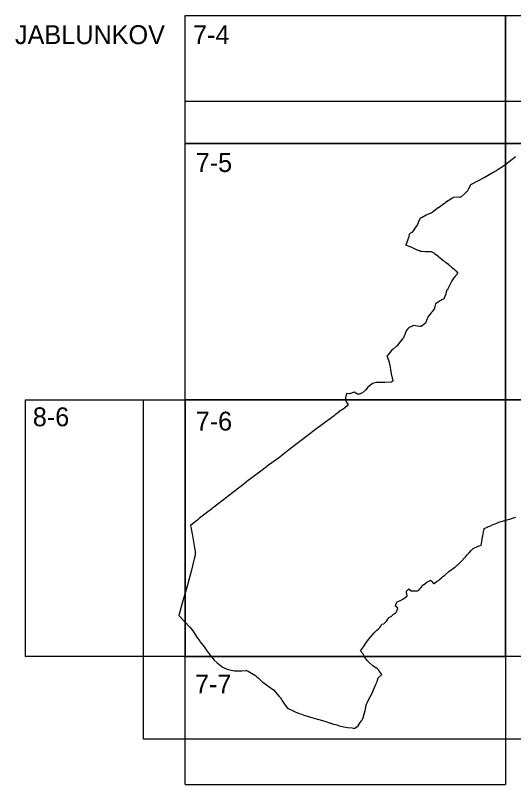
# Model space of a CAD drawing. Extents: x -447352 to -425530, y -1135906 to -1121091.
# Drawn here: x -443419.6 to -443176.6, y -1126653.4 to -1126278.4 of the extents above; entities that cross this region are included whole.
import ezdxf

# ---------------------------------------------------------------- set-up
doc = ezdxf.new("R2010")
doc.units = 0
for name, color, linetype in [('Vrstva 1', 7, 'Continuous'), ('Vrstva 10', 7, 'Continuous'), ('Vrstva 4', 7, 'Continuous')]:
    doc.layers.add(name, color=color, linetype=linetype)

msp = doc.modelspace()

# ---------------------------------------------------------------- linework, layer by layer
at = {"layer": 'Vrstva 1'}
for points in [[(-443175.66, -1126347.4), (-443176.81, -1126348.27), (-443177.38, -1126348.7), (-443177.96, -1126349.14), (-443178.12, -1126349.26), (-443180.25, -1126350.9), (-443181.32, -1126351.72), (-443181.79, -1126352.06), (-443182.55, -1126352.57), (-443182.8, -1126352.73), (-443183.39, -1126353.12), (-443183.43, -1126353.15), (-443183.64, -1126353.29), (-443184.55, -1126353.89), (-443184.56, -1126353.89), (-443185.03, -1126354.15), (-443185.18, -1126354.23), (-443185.36, -1126354.33), (-443185.82, -1126354.58), (-443186, -1126354.69), (-443186.16, -1126354.78), (-443186.26, -1126354.84), (-443186.5, -1126354.98), (-443188.16, -1126355.92), (-443188.33, -1126356.01), (-443188.56, -1126356.14), (-443191.03, -1126357.54), (-443191.15, -1126357.61), (-443193.26, -1126358.74), (-443194.28, -1126359.29), (-443197.62, -1126361.1), (-443197.79, -1126361.4), (-443197.85, -1126361.51), (-443198.63, -1126362.97), (-443199.31, -1126364.29), (-443199.45, -1126364.42), (-443199.54, -1126364.5), (-443200.68, -1126365.54), (-443202.19, -1126366.92), (-443202.36, -1126367.07), (-443202.36, -1126367.08), (-443202.83, -1126367.09), (-443206.02, -1126367.18), (-443206.03, -1126367.18), (-443206.46, -1126367.47), (-443207.29, -1126368.04), (-443209.76, -1126369.7), (-443209.8, -1126369.72), (-443210.04, -1126369.9), (-443210.31, -1126370.1), (-443213.29, -1126372.23), (-443213.36, -1126372.28), (-443216.36, -1126374.46), (-443216.83, -1126374.8), (-443216.99, -1126374.86), (-443218.93, -1126375.58), (-443218.94, -1126375.58), (-443219.33, -1126375.82), (-443221.21, -1126376.98), (-443222.13, -1126377.19), (-443222.38, -1126377.7), (-443223.14, -1126379.21), (-443223.15, -1126379.22), (-443223.22, -1126379.48), (-443223.42, -1126380.32), (-443224.25, -1126381.43), (-443225.62, -1126383.38), (-443226.18, -1126384.19), (-443226.21, -1126384.21), (-443227.37, -1126384.85), (-443227.47, -1126384.91), (-443227.54, -1126385.3), (-443227.69, -1126386.11), (-443227.74, -1126386.3), (-443229.03, -1126389.88), (-443229.2, -1126390.36), (-443229.17, -1126390.35), (-443229.15, -1126390.34), (-443228.47, -1126390.6), (-443226.66, -1126391.26), (-443226.04, -1126391.55), (-443223.75, -1126392.63), (-443223.73, -1126392.63), (-443222.57, -1126393.1), (-443222.1, -1126393.28), (-443222.07, -1126393.29), (-443221.64, -1126393.32), (-443221.5, -1126393.33), (-443221.28, -1126393.35), (-443219.68, -1126393.45), (-443218.64, -1126393.52), (-443217.59, -1126393.49), (-443216.75, -1126393.46), (-443216.74, -1126393.46), (-443216.46, -1126393.61), (-443216.09, -1126393.87), (-443215.54, -1126394.25), (-443215.15, -1126394.53), (-443213.59, -1126395.67), (-443213.42, -1126395.79), (-443212.31, -1126396.71), (-443211.92, -1126397.03), (-443211.74, -1126397.18), (-443210.99, -1126397.79), (-443210.72, -1126398.02), (-443210.12, -1126398.51), (-443209.9, -1126398.69), (-443209.26, -1126399.11), (-443208.51, -1126399.61), (-443208.48, -1126399.63), (-443207.72, -1126400.31), (-443206.84, -1126401.09), (-443206.4, -1126401.47), (-443205.39, -1126402.36), (-443205.13, -1126402.59), (-443205.08, -1126402.64), (-443204.98, -1126402.74), (-443204.97, -1126402.75), (-443204.88, -1126402.85), (-443204.85, -1126402.88), (-443203.8, -1126404.11), (-443203.81, -1126404.12), (-443204.25, -1126404.61), (-443204.31, -1126404.68), (-443204.88, -1126405.31), (-443205.7, -1126406.37), (-443205.87, -1126406.58), (-443206.43, -1126407.3), (-443206.73, -1126407.83), (-443206.75, -1126407.87), (-443206.76, -1126407.89), (-443206.89, -1126408.17), (-443207.69, -1126409.84), (-443208, -1126410.48), (-443208.62, -1126411.77), (-443208.73, -1126412.01), (-443208.74, -1126412.01), (-443208.78, -1126412.04), (-443209.07, -1126412.24), (-443209.15, -1126412.28), (-443209.2, -1126412.38), (-443209.29, -1126412.58), (-443209.38, -1126412.86), (-443209.55, -1126413.42), (-443209.56, -1126413.44), (-443209.68, -1126413.94), (-443209.7, -1126414.01), (-443209.69, -1126414.07), (-443209.68, -1126414.15), (-443209.68, -1126414.22), (-443209.69, -1126414.27), (-443210.57, -1126416.6), (-443210.59, -1126416.65), (-443210.61, -1126416.69), (-443210.62, -1126416.7), (-443211.32, -1126417), (-443211.57, -1126417.11), (-443212.04, -1126417.35), (-443214.65, -1126419.04), (-443214.65, -1126419.04), (-443215.02, -1126420.35), (-443215.1, -1126420.61), (-443215.21, -1126421.03), (-443215.27, -1126421.24), (-443215.27, -1126421.25), (-443215.26, -1126421.25), (-443215.09, -1126421.41), (-443215.1, -1126421.42), (-443215.46, -1126421.81), (-443216.26, -1126422.81), (-443216.27, -1126422.82), (-443216.48, -1126423.07), (-443216.48, -1126423.08), (-443216.6, -1126423.23), (-443217.76, -1126424.58), (-443218.3, -1126425.21), (-443219.06, -1126427.16), (-443219.44, -1126428.18), (-443219.57, -1126428.53), (-443221.1, -1126429.63), (-443221.72, -1126430.07), (-443221.9, -1126430.11), (-443221.92, -1126430.11), (-443222.55, -1126430.02), (-443225.39, -1126429.6), (-443225.88, -1126429.84), (-443227.21, -1126430.48), (-443227.75, -1126430.74), (-443227.78, -1126430.77), (-443228.21, -1126431.18), (-443228.38, -1126431.4), (-443229.04, -1126432.25), (-443229.04, -1126432.26), (-443229.71, -1126434.06), (-443230.28, -1126435.56), (-443230.28, -1126435.56), (-443230.42, -1126435.78), (-443230.75, -1126436.15), (-443231.47, -1126436.95), (-443232.17, -1126437.72), (-443232.18, -1126437.74), (-443232.31, -1126437.93), (-443233.38, -1126439.5), (-443233.85, -1126439.88), (-443235.42, -1126441.14), (-443236.09, -1126441.68), (-443236.19, -1126441.76), (-443236.22, -1126441.8), (-443237.34, -1126443.23), (-443238.48, -1126444.54), (-443238.33, -1126444.71), (-443238.32, -1126444.74), (-443238.32, -1126444.75), (-443237.31, -1126447.51), (-443237.03, -1126449.17), (-443236.71, -1126451.12), (-443236.3, -1126453.08), (-443235.57, -1126456.58), (-443235.53, -1126456.78), (-443236.18, -1126457.12), (-443236.3, -1126457.19), (-443239.47, -1126457.45), (-443239.63, -1126457.45), (-443241.12, -1126457.42), (-443243.51, -1126457.4), (-443244.79, -1126457.67), (-443245.39, -1126457.94), (-443246.37, -1126458.74), (-443247.67, -1126459.61), (-443247.76, -1126459.72), (-443248.92, -1126461.14), (-443250.37, -1126462.48), (-443251.06, -1126462.8), (-443251.66, -1126463.08), (-443252.83, -1126463.01), (-443254.44, -1126462.16), (-443256.68, -1126462.83), (-443258.16, -1126462.8), (-443258.54, -1126464.91), (-443258.55, -1126464.93), (-443258.56, -1126465.02), (-443258.27, -1126466.83), (-443257.3, -1126468.15), (-443257.29, -1126468.17), (-443258.03, -1126468.92), (-443258.64, -1126469.48), (-443258.89, -1126469.71), (-443259.69, -1126470.34), (-443261.62, -1126471.57), (-443261.68, -1126471.61), (-443263.65, -1126473.14), (-443263.71, -1126473.18), (-443264.2, -1126473.56), (-443268.86, -1126477.02), (-443268.89, -1126477.05), (-443273.84, -1126480.81), (-443278.1, -1126484.06), (-443278.98, -1126484.72), (-443281.55, -1126486.66), (-443285.55, -1126489.79), (-443287.99, -1126491.66), (-443291.3, -1126494.19), (-443291.35, -1126494.23), (-443296.14, -1126497.74), (-443296.37, -1126497.92), (-443299.98, -1126500.6), (-443302.37, -1126502.42), (-443304.34, -1126503.9), (-443306.66, -1126505.65), (-443306.89, -1126505.82), (-443308.02, -1126506.71), (-443312.84, -1126510.51), (-443316.73, -1126513.46), (-443320.95, -1126516.71), (-443322.24, -1126517.71), (-443324.63, -1126519.59), (-443325.81, -1126520.51), (-443329.75, -1126523.56), (-443330.68, -1126524.27), (-443331.92, -1126525.23), (-443334.24, -1126527.03), (-443334.24, -1126527.03), (-443334.2, -1126527.21), (-443333.91, -1126528.59), (-443333.88, -1126528.75), (-443333.35, -1126531.29), (-443333.19, -1126532.02), (-443333.19, -1126532.06), (-443332.26, -1126537.94), (-443332.25, -1126537.97), (-443331.95, -1126539.7), (-443331.95, -1126539.72), (-443331.89, -1126540.09), (-443331.83, -1126540.51), (-443331.86, -1126540.88), (-443332.01, -1126541.61), (-443332.39, -1126543.4), (-443332.68, -1126544.58), (-443332.7, -1126544.63), (-443333.81, -1126548.8), (-443335.91, -1126556.68), (-443337.9, -1126563.9), (-443339.83, -1126571), (-443339.84, -1126571.04), (-443334.56, -1126576.64), (-443333.51, -1126577.77), (-443332.75, -1126578.99), (-443330.73, -1126582.05), (-443330.68, -1126582.12), (-443329.67, -1126583.53), (-443329.51, -1126583.74), (-443327.63, -1126586.22), (-443327.06, -1126586.96), (-443327.03, -1126587), (-443326.51, -1126587.72), (-443325.13, -1126589.62), (-443324.8, -1126590.07), (-443322.65, -1126592.79), (-443321.25, -1126594.01), (-443318.85, -1126595.99), (-443317.11, -1126596.74), (-443315.92, -1126597.26), (-443315.79, -1126597.31), (-443314.46, -1126597.59), (-443314.32, -1126597.62), (-443312.7, -1126597.95), (-443312.67, -1126597.95), (-443311.71, -1126597.93), (-443311.33, -1126597.93), (-443310.81, -1126597.92), (-443310.13, -1126597.91), (-443309.22, -1126597.87), (-443307.27, -1126597.71), (-443306.82, -1126597.78), (-443306.16, -1126598.13), (-443304.44, -1126599.08), (-443302.48, -1126600.18), (-443301.96, -1126600.66), (-443301.24, -1126601.34), (-443300.44, -1126602.09), (-443299.12, -1126603.39), (-443298.98, -1126603.49), (-443297.79, -1126604.34), (-443295.38, -1126606.05), (-443293.74, -1126607.23), (-443292.69, -1126608.41), (-443291.05, -1126610.23), (-443290.41, -1126610.94), (-443290.05, -1126611.53), (-443289.59, -1126612.27), (-443288.65, -1126613.74), (-443288.02, -1126614.66), (-443286.98, -1126616.1), (-443285.91, -1126616.61), (-443284.53, -1126617.26), (-443283.22, -1126617.87), (-443281.25, -1126618.76), (-443280.12, -1126619.11), (-443278.4, -1126619.68), (-443278.25, -1126619.73), (-443277.16, -1126620.05), (-443275.74, -1126620.47), (-443275.73, -1126620.47), (-443275.52, -1126620.53), (-443275.46, -1126620.55), (-443274.6, -1126620.81), (-443272.21, -1126621.5), (-443272.09, -1126621.54), (-443271.61, -1126621.68), (-443268.68, -1126622.55), (-443265.99, -1126623.38), (-443265.65, -1126623.48), (-443264.89, -1126623.71), (-443262.88, -1126624.33), (-443261.15, -1126624.88), (-443257.69, -1126625.62)], [(-443257.69, -1126625.62), (-443255.3, -1126625.81), (-443254.1, -1126626.04), (-443253.99, -1126625.95), (-443252.41, -1126624.68), (-443251.38, -1126623.2), (-443251.27, -1126623.05), (-443250.75, -1126622.29), (-443250.64, -1126622.12), (-443250.5, -1126621.89), (-443250.12, -1126621.26), (-443249.85, -1126620.43), (-443249.83, -1126620.36), (-443249.81, -1126620.31), (-443249.78, -1126620.2), (-443249.75, -1126620.11), (-443249.75, -1126620.1), (-443249.12, -1126617.9), (-443248.98, -1126617.38), (-443248.53, -1126614.63), (-443248.53, -1126614.63), (-443248.34, -1126614.19), (-443248.08, -1126613.57), (-443247.29, -1126611.74), (-443245.72, -1126609.09), (-443243.97, -1126604.96), (-443243.65, -1126604.32), (-443243.61, -1126604.19), (-443243.22, -1126603.09), (-443242.63, -1126601.42), (-443240.95, -1126599.71), (-443241.88, -1126598.47), (-443241.94, -1126598.38), (-443241.99, -1126598.32), (-443242.02, -1126598.28), (-443242.09, -1126598.18), (-443242.14, -1126598.1), (-443242.22, -1126597.98), (-443242.58, -1126597.46), (-443242.95, -1126597), (-443243.52, -1126596.63), (-443243.62, -1126596.57), (-443245.27, -1126595.5), (-443247.46, -1126593.56), (-443247.59, -1126593.39), (-443247.62, -1126593.35), (-443247.7, -1126593.25), (-443248.04, -1126592.83), (-443248.37, -1126592.42), (-443248.63, -1126592.1), (-443249.11, -1126591.51), (-443249.19, -1126591.41), (-443249.69, -1126590.45), (-443249.98, -1126589.89), (-443250.21, -1126589.46), (-443250.26, -1126589.37), (-443250.3, -1126589.32), (-443250.56, -1126589.03), (-443250.76, -1126588.8), (-443251.02, -1126588.51), (-443251.24, -1126588.26), (-443249.38, -1126585.52), (-443249.29, -1126585.4), (-443248.97, -1126584.95), (-443248.65, -1126584.51), (-443247.32, -1126582.68), (-443244.64, -1126579.42), (-443244.29, -1126579.1), (-443243.58, -1126578.4), (-443243.47, -1126578.31), (-443243.28, -1126578.17), (-443242.68, -1126577.69), (-443241.82, -1126576.85), (-443241.41, -1126576.09), (-443240.94, -1126575.22), (-443239.89, -1126574.98), (-443238.49, -1126573.55), (-443237.95, -1126572.7), (-443237.94, -1126572.69), (-443237.94, -1126572.67), (-443237.73, -1126572.34), (-443237.68, -1126572.26), (-443237.44, -1126571.87), (-443236.28, -1126571.43), (-443235.26, -1126570.25), (-443234.73, -1126570.05), (-443234.61, -1126570), (-443234.19, -1126569.84), (-443233.97, -1126569.45), (-443233.92, -1126569.36), (-443233.75, -1126569.06), (-443233.34, -1126568.32), (-443233.14, -1126567.41), (-443233.14, -1126567.39), (-443233.13, -1126567.38), (-443234.18, -1126566.39), (-443234.2, -1126566.38), (-443234.21, -1126566.36), (-443234.26, -1126566.32), (-443233.61, -1126564.52), (-443233.54, -1126564.32), (-443233.38, -1126564.26), (-443232.65, -1126563.97), (-443231.96, -1126563.7), (-443231.84, -1126563.65), (-443230.63, -1126562.94), (-443230.51, -1126562.86), (-443230.51, -1126562.86), (-443230.5, -1126562.85), (-443230.38, -1126562.78), (-443228.52, -1126561.38), (-443228.52, -1126561.34), (-443228.55, -1126561.18), (-443228.62, -1126560.7), (-443228.68, -1126560.35), (-443228.78, -1126559.73), (-443228.8, -1126559.62), (-443228.82, -1126559.49), (-443228.84, -1126559.32), (-443228.87, -1126559.18), (-443228.33, -1126558.62), (-443227.77, -1126558.05), (-443227.73, -1126558), (-443227.59, -1126558.1), (-443226.59, -1126558.89), (-443225.91, -1126558.9), (-443225.85, -1126558.9), (-443225.6, -1126558.91), (-443225.44, -1126558.91), (-443224.13, -1126558.93), (-443223.5, -1126558.95), (-443223.23, -1126558.79), (-443223.2, -1126558.77), (-443223.08, -1126558.7), (-443222.94, -1126558.61), (-443222.9, -1126558.58), (-443222.36, -1126557.98), (-443222.25, -1126557.86), (-443222.16, -1126557.76), (-443221.99, -1126557.58), (-443221.91, -1126557.49), (-443221.8, -1126557.37), (-443221.77, -1126557.33), (-443221.74, -1126557.3), (-443221.69, -1126557.24), (-443221.6, -1126557.13), (-443221.2, -1126556.63), (-443220.99, -1126556.37), (-443220.74, -1126556.05), (-443220.63, -1126555.97), (-443219.17, -1126554.9), (-443218.96, -1126554.77), (-443217.6, -1126554), (-443217.2, -1126553.77), (-443217.2, -1126553.77), (-443217.06, -1126553.92), (-443216.35, -1126554.63), (-443215.98, -1126555.01), (-443215.8, -1126555.18), (-443215.65, -1126555.33), (-443215.56, -1126555.29), (-443214.28, -1126554.52), (-443214.19, -1126554.47), (-443213.26, -1126553.91), (-443213.22, -1126553.88), (-443212.89, -1126553.59), (-443212.84, -1126553.55), (-443212.67, -1126553.4), (-443212.66, -1126553.39), (-443212.66, -1126553.39), (-443212.62, -1126553.35), (-443212.58, -1126553.31), (-443211.69, -1126552.5), (-443211.67, -1126552.49), (-443211.08, -1126551.95), (-443210.97, -1126551.86), (-443210.86, -1126551.76), (-443210.86, -1126551.76), (-443210.85, -1126551.76), (-443210.85, -1126551.76), (-443210.85, -1126551.75), (-443210.84, -1126551.75), (-443210.83, -1126551.74), (-443210.83, -1126551.74), (-443210.82, -1126551.73), (-443210.82, -1126551.73), (-443210.81, -1126551.73), (-443210.81, -1126551.73), (-443210.23, -1126551.24), (-443208.24, -1126549.56), (-443207.04, -1126548.71), (-443206.92, -1126548.63), (-443206.87, -1126548.59), (-443206.85, -1126548.58), (-443206.8, -1126548.55), (-443206.44, -1126548.28), (-443205.2, -1126547.34), (-443205.02, -1126547.2), (-443204.81, -1126547.04), (-443204.79, -1126547.02), (-443203.91, -1126546.35), (-443203.56, -1126546.08), (-443203.51, -1126546.02), (-443203.42, -1126545.92), (-443202.78, -1126545.24), (-443201.88, -1126544.26), (-443200.52, -1126542.85), (-443200.3, -1126542.62), (-443200.05, -1126542.34), (-443199.21, -1126541.39), (-443198.92, -1126541.07), (-443198.72, -1126540.86), (-443198.43, -1126540.54), (-443197.25, -1126539.35), (-443196.32, -1126538.33), (-443194.26, -1126537.32), (-443194.1, -1126537.27), (-443193.9, -1126537.19), (-443192.46, -1126536.7), (-443192.31, -1126535.83), (-443192.15, -1126534.96), (-443191.73, -1126532.59), (-443191.65, -1126532.12), (-443191.32, -1126530.24), (-443191.12, -1126529.36), (-443191.09, -1126529.24), (-443191.04, -1126529.05), (-443191.03, -1126529.01), (-443191.01, -1126528.94), (-443191, -1126528.9), (-443190.99, -1126528.85), (-443190.98, -1126528.81), (-443190.97, -1126528.79), (-443190.91, -1126528.58), (-443189.83, -1126528.04), (-443189.54, -1126527.9), (-443189.52, -1126527.89), (-443189.27, -1126527.76), (-443189.22, -1126527.74), (-443187.45, -1126527.02), (-443187.42, -1126527.01), (-443187.39, -1126526.99), (-443186.59, -1126526.68), (-443185.63, -1126526.28), (-443184.82, -1126525.94), (-443183.88, -1126525.55), (-443183.8, -1126525.52), (-443183.19, -1126525.28), (-443183.34, -1126525.44), (-443183.1, -1126525.35), (-443182.61, -1126525.15), (-443182.08, -1126524.99), (-443180.38, -1126524.47), (-443179.79, -1126524.3), (-443179.34, -1126524.18), (-443178.45, -1126523.93), (-443177.14, -1126523.55), (-443175.6, -1126523.09)]]:
    msp.add_lwpolyline(points, dxfattribs=at)
at = {"layer": 'Vrstva 10'}
msp.add_lwpolyline([(-443024.3, -1126320.23), (-443024.3, -1126631.21), (-443357.17, -1126631.21), (-443357.17, -1126465.91), (-443336.8, -1126465.91), (-443336.8, -1126340.91), (-443336.8, -1126320.23), (-443024.3, -1126320.23)], dxfattribs=at)
at = {"layer": 'Vrstva 4'}
for p, q in [((-443336.8, -1126278.41), (-443024.3, -1126278.41)), ((-443414.93, -1126465.91), (-443414.93, -1126590.91)), ((-443336.8, -1126653.41), (-443180.55, -1126653.41))]:
    msp.add_line(p, q, dxfattribs=at)
for points in [[(-443180.55, -1126278.41), (-443180.55, -1126340.91), (-443336.8, -1126340.91), (-443336.8, -1126278.41)], [(-443024.3, -1126278.41), (-443024.3, -1126340.91), (-443180.55, -1126340.91), (-443180.55, -1126278.41)], [(-443414.93, -1126465.91), (-443336.8, -1126465.91), (-443336.8, -1126590.91), (-443414.93, -1126590.91)], [(-443336.8, -1126653.41), (-443336.8, -1126590.91), (-443180.55, -1126590.91), (-443180.55, -1126653.41)]]:
    msp.add_lwpolyline(points, dxfattribs=at)
for points in [[(-443180.55, -1126340.91), (-443180.55, -1126465.91), (-443336.8, -1126465.91), (-443336.8, -1126340.91)], [(-443024.3, -1126340.91), (-443024.3, -1126465.91), (-443180.55, -1126465.91), (-443180.55, -1126340.91)], [(-443180.55, -1126465.91), (-443180.55, -1126590.91), (-443336.8, -1126590.91), (-443336.8, -1126465.91)], [(-443024.3, -1126465.91), (-443024.3, -1126590.91), (-443180.55, -1126590.91), (-443180.55, -1126465.91)]]:
    msp.add_lwpolyline(points, close=True, dxfattribs=at)

# ---------------------------------------------------------------- texts
at = {"layer": 'Vrstva 1'}
for s, p in [('JABLUNKOV', (-443419.84, -1126292.41)), ('7-4', (-443332.99, -1126292.41)), ('7-5', (-443331.68, -1126354.75)), ('8-6', (-443411.15, -1126478.72)), ('7-6', (-443331.68, -1126480.82)), ('7-7', (-443332.04, -1126608.99))]:
    msp.add_text(s, height=9.2, dxfattribs=at).set_placement(p)

doc.saveas('drawing.dxf')
